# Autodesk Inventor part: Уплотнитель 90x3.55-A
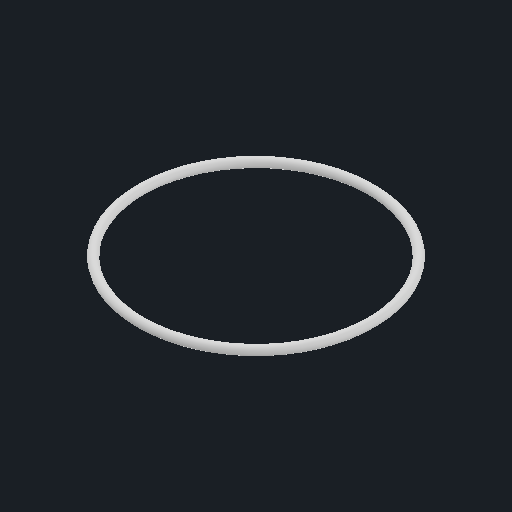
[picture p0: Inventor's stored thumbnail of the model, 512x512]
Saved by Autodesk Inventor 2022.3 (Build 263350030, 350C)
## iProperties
Created: 2020-09
Part Number: Уплотнитель 90x3.55-A
Material: Типовые
Document SubType Name: Modeling
Designer: Карташов
Density: 1 g/cm^3
Appearance: По умолчанию
Title: D:\мои документы\Ирина\_WorldSkills\2020_09 ФНЧ\Module A\Участникам\GIVEN\Уплотнитель 90x3.55-A.stp
Author: Дом
Sending System: Autodesk Inventor 2021
Preprocessor: ST-DEVELOPER v18.1
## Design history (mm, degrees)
feature "Твердое тело2"
node "Твердое тело1"
